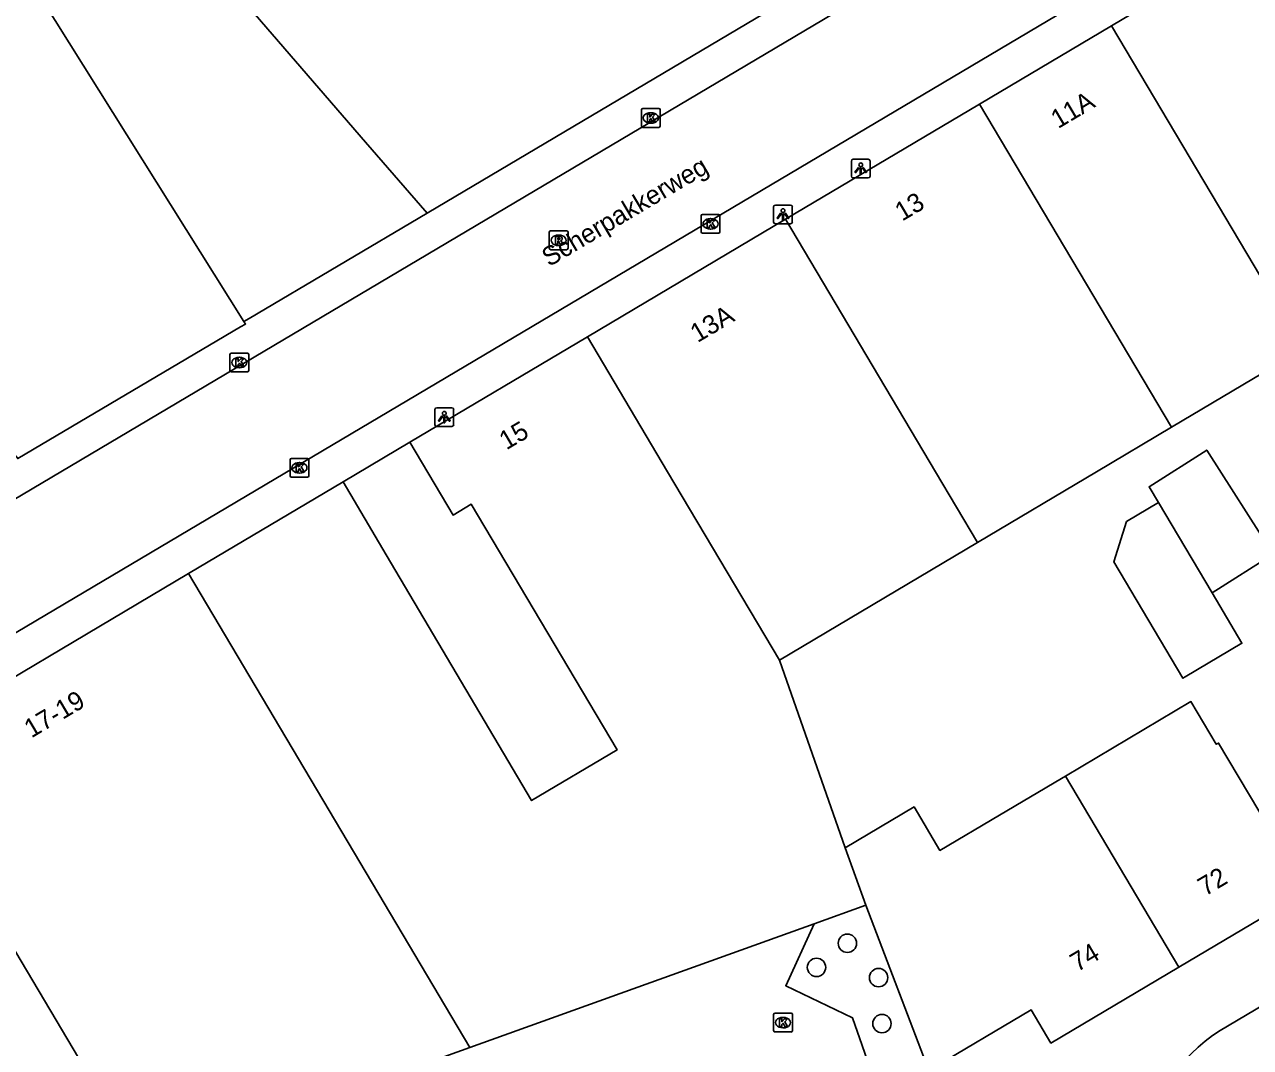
# Model space of a CAD drawing. Extents: x 159503 to 160347, y 382525 to 383272.
# Drawn here: x 159623.7 to 159688.9, y 382969.4 to 383023.8 of the extents above; entities that cross this region are included whole.
import ezdxf

# ---------------------------------------------------------------- set-up
doc = ezdxf.new("R2010")
doc.units = 0
for name, color, linetype in [('IMGEO_Boom', 7, 'Continuous'), ('IMGEO_Kolk', 7, 'Continuous'), ('IMGEO_Lichtpunt', 7, 'Continuous'), ('IMGEO_Openbare_ruimte_label', 7, 'Continuous'), ('IMGEO_Pand', 7, 'Continuous'), ('IMGEO_Pand_nummerreeks', 7, 'Continuous'), ('IMGEO_Parkeervlak_open', 7, 'Continuous'), ('IMGEO_Rijbaan_lokaal_open', 7, 'Continuous'), ('IMGEO_Rioolput', 7, 'Continuous'), ('IMGEO_Voetpad_open', 7, 'Continuous')]:
    doc.layers.add(name, color=color, linetype=linetype)

msp = doc.modelspace()

# ---------------------------------------------------------------- linework, layer by layer
at = {"layer": 'IMGEO_Boom'}
for centre in [(159667.462, 382974.908), (159665.819, 382973.625), (159669.12, 382973.079), (159669.302, 382970.634)]:
    msp.add_circle(centre, 0.489, dxfattribs=at)
at = {"layer": 'IMGEO_Kolk'}
for p, q in [((159656.504, 383018.408), (159656.504, 383019.26)), ((159656.579, 383019.334), (159657.431, 383019.334)), ((159657.505, 383019.26), (159657.505, 383018.408)), ((159657.015, 383018.554), (159656.99, 383018.554)), ((159656.992, 383019.114), (159657.017, 383019.114)), ((159657.431, 383018.334), (159656.579, 383018.334)), ((159659.68, 383012.776), (159659.68, 383013.628)), ((159659.755, 383013.702), (159660.607, 383013.702)), ((159660.168, 383013.482), (159660.193, 383013.482)), ((159660.681, 383013.628), (159660.681, 383012.776)), ((159660.607, 383012.702), (159659.755, 383012.702)), ((159660.191, 383012.922), (159660.166, 383012.922)), ((159634.611, 383005.389), (159634.611, 383006.241)), ((159634.686, 383006.315), (159635.538, 383006.315)), ((159635.612, 383006.241), (159635.612, 383005.389)), ((159635.122, 383005.535), (159635.097, 383005.535)), ((159635.099, 383006.095), (159635.124, 383006.095)), ((159635.538, 383005.315), (159634.686, 383005.315)), ((159637.809, 382999.786), (159637.809, 383000.638)), ((159637.884, 383000.712), (159638.736, 383000.712)), ((159638.297, 383000.492), (159638.322, 383000.492)), ((159638.81, 383000.638), (159638.81, 382999.786)), ((159638.736, 382999.712), (159637.884, 382999.712)), ((159638.32, 382999.932), (159638.295, 382999.932)), ((159663.536, 382970.26), (159663.536, 382971.112)), ((159663.611, 382971.186), (159664.463, 382971.186)), ((159664.024, 382970.966), (159664.049, 382970.966)), ((159664.537, 382971.112), (159664.537, 382970.26)), ((159664.047, 382970.406), (159664.022, 382970.406)), ((159664.463, 382970.186), (159663.611, 382970.186))]:
    msp.add_line(p, q, dxfattribs=at)
for points in [[(159656.504, 383018.408), (159656.504, 383019.26)], [(159656.579, 383019.334), (159657.431, 383019.334)], [(159657.505, 383019.26), (159657.505, 383018.408)], [(159656.825, 383019.034), (159656.948, 383019.034), (159656.948, 383018.883), (159657.078, 383019.034), (159657.242, 383019.034), (159657.096, 383018.883), (159657.249, 383018.634), (159657.097, 383018.634), (159657.012, 383018.798), (159656.948, 383018.731), (159656.948, 383018.634), (159656.825, 383018.634), (159656.825, 383019.034)], [(159657.431, 383018.334), (159656.579, 383018.334)], [(159659.68, 383012.776), (159659.68, 383013.628)], [(159659.755, 383013.702), (159660.607, 383013.702)], [(159660.001, 383013.402), (159660.124, 383013.402), (159660.124, 383013.251), (159660.254, 383013.402), (159660.418, 383013.402), (159660.272, 383013.251), (159660.425, 383013.002), (159660.273, 383013.002), (159660.188, 383013.166), (159660.124, 383013.099), (159660.124, 383013.002), (159660.001, 383013.002), (159660.001, 383013.402)], [(159660.681, 383013.628), (159660.681, 383012.776)], [(159660.607, 383012.702), (159659.755, 383012.702)], [(159634.611, 383005.389), (159634.611, 383006.241)], [(159634.686, 383006.315), (159635.538, 383006.315)], [(159635.612, 383006.241), (159635.612, 383005.389)], [(159634.932, 383006.015), (159635.055, 383006.015), (159635.055, 383005.864), (159635.185, 383006.015), (159635.349, 383006.015), (159635.203, 383005.864), (159635.356, 383005.615), (159635.204, 383005.615), (159635.119, 383005.779), (159635.055, 383005.712), (159635.055, 383005.615), (159634.932, 383005.615), (159634.932, 383006.015)], [(159635.538, 383005.315), (159634.686, 383005.315)], [(159637.809, 382999.786), (159637.809, 383000.638)], [(159637.884, 383000.712), (159638.736, 383000.712)], [(159638.13, 383000.412), (159638.253, 383000.412), (159638.253, 383000.261), (159638.383, 383000.412), (159638.547, 383000.412), (159638.401, 383000.261), (159638.554, 383000.012), (159638.402, 383000.012), (159638.317, 383000.176), (159638.253, 383000.109), (159638.253, 383000.012), (159638.13, 383000.012), (159638.13, 383000.412)], [(159638.81, 383000.638), (159638.81, 382999.786)], [(159638.736, 382999.712), (159637.884, 382999.712)], [(159663.536, 382970.26), (159663.536, 382971.112)], [(159663.611, 382971.186), (159664.463, 382971.186)], [(159664.537, 382971.112), (159664.537, 382970.26)], [(159663.857, 382970.886), (159663.98, 382970.886), (159663.98, 382970.735), (159664.11, 382970.886), (159664.274, 382970.886), (159664.128, 382970.735), (159664.281, 382970.486), (159664.129, 382970.486), (159664.044, 382970.65), (159663.98, 382970.583), (159663.98, 382970.486), (159663.857, 382970.486), (159663.857, 382970.886)], [(159664.463, 382970.186), (159663.611, 382970.186)]]:
    msp.add_lwpolyline(points, dxfattribs=at)
for centre, start, end in [((159656.581, 383019.258), 91.55205, 178.44795), ((159656.581, 383019.258), 91.55205, 178.44795), ((159657.429, 383019.258), 1.55205, 88.44795), ((159657.429, 383019.258), 1.55205, 88.44795), ((159656.581, 383018.41), 181.55205, 268.44795), ((159656.581, 383018.41), 181.55205, 268.44795), ((159657.429, 383018.41), 271.55205, 358.44795), ((159657.429, 383018.41), 271.55205, 358.44795), ((159659.757, 383013.626), 91.55205, 178.44795), ((159659.757, 383013.626), 91.55205, 178.44795), ((159660.605, 383013.626), 1.55205, 88.44795), ((159660.605, 383013.626), 1.55205, 88.44795), ((159659.757, 383012.778), 181.55205, 268.44795), ((159659.757, 383012.778), 181.55205, 268.44795), ((159660.605, 383012.778), 271.55205, 358.44795), ((159660.605, 383012.778), 271.55205, 358.44795), ((159634.688, 383006.239), 91.55205, 178.44795), ((159634.688, 383006.239), 91.55205, 178.44795), ((159635.536, 383006.239), 1.55205, 88.44795), ((159635.536, 383006.239), 1.55205, 88.44795), ((159634.688, 383005.391), 181.55205, 268.44795), ((159634.688, 383005.391), 181.55205, 268.44795), ((159635.536, 383005.391), 271.55205, 358.44795), ((159635.536, 383005.391), 271.55205, 358.44795), ((159637.886, 383000.636), 91.55205, 178.44795), ((159637.886, 383000.636), 91.55205, 178.44795), ((159638.734, 383000.636), 1.55205, 88.44795), ((159638.734, 383000.636), 1.55205, 88.44795), ((159637.886, 382999.788), 181.55205, 268.44795), ((159637.886, 382999.788), 181.55205, 268.44795), ((159638.734, 382999.788), 271.55205, 358.44795), ((159638.734, 382999.788), 271.55205, 358.44795), ((159663.613, 382971.11), 91.55205, 178.44795), ((159663.613, 382971.11), 91.55205, 178.44795), ((159664.461, 382971.11), 1.55205, 88.44795), ((159664.461, 382971.11), 1.55205, 88.44795), ((159663.613, 382970.262), 181.55205, 268.44795), ((159663.613, 382970.262), 181.55205, 268.44795), ((159664.461, 382970.262), 271.55205, 358.44795), ((159664.461, 382970.262), 271.55205, 358.44795)]:
    msp.add_arc(centre, 0.0765, start, end, dxfattribs=at)
for centre, major_axis, ratio, start_param, end_param in [((159656.991, 383018.834), (-0.387, 0.002), 0.722429, 4.712389, 7.853982), ((159657.016, 383018.834), (-0.39, 0.002), 0.717154, 1.570796, 4.712389), ((159660.167, 383013.202), (-0.387, 0.002), 0.722429, 4.712389, 7.853982), ((159660.192, 383013.202), (-0.39, 0.002), 0.717154, 1.570796, 4.712389), ((159635.098, 383005.815), (-0.387, 0.002), 0.722429, 4.712389, 7.853982), ((159635.123, 383005.815), (-0.39, 0.002), 0.717154, 1.570796, 4.712389), ((159638.296, 383000.212), (-0.387, 0.002), 0.722429, 4.712389, 7.853982), ((159638.321, 383000.212), (-0.39, 0.002), 0.717154, 1.570796, 4.712389), ((159664.023, 382970.686), (-0.387, 0.002), 0.722429, 4.712389, 7.853982), ((159664.048, 382970.686), (-0.39, 0.002), 0.717154, 1.570796, 4.712389)]:
    msp.add_ellipse(centre, major_axis=major_axis, ratio=ratio, start_param=start_param, end_param=end_param, dxfattribs=at)
at = {"layer": 'IMGEO_Lichtpunt'}
for p, q in [((159668.575, 383016.636), (159667.767, 383016.636)), ((159668.575, 383016.636), (159667.767, 383016.636)), ((159667.673, 383016.541), (159667.673, 383015.734)), ((159667.673, 383016.541), (159667.673, 383015.734)), ((159668.669, 383015.734), (159668.669, 383016.541)), ((159668.669, 383015.734), (159668.669, 383016.541)), ((159667.767, 383015.64), (159668.575, 383015.64)), ((159667.767, 383015.64), (159668.575, 383015.64)), ((159663.536, 383014.103), (159663.536, 383013.296)), ((159663.536, 383014.103), (159663.536, 383013.296)), ((159664.438, 383014.198), (159663.63, 383014.198)), ((159664.438, 383014.198), (159663.63, 383014.198)), ((159664.532, 383013.296), (159664.532, 383014.103)), ((159664.532, 383013.296), (159664.532, 383014.103)), ((159663.63, 383013.202), (159664.438, 383013.202)), ((159663.63, 383013.202), (159664.438, 383013.202)), ((159645.518, 383003.315), (159645.518, 383002.508)), ((159645.518, 383003.315), (159645.518, 383002.508)), ((159646.42, 383003.41), (159645.612, 383003.41)), ((159646.42, 383003.41), (159645.612, 383003.41)), ((159646.514, 383002.508), (159646.514, 383003.315)), ((159646.514, 383002.508), (159646.514, 383003.315)), ((159645.612, 383002.414), (159646.42, 383002.414)), ((159645.612, 383002.414), (159646.42, 383002.414))]:
    msp.add_line(p, q, dxfattribs=at)
for points in [[(159668.047, 383016.205), (159668.086, 383016.177), (159667.898, 383015.915), (159667.86, 383015.942), (159668.047, 383016.205)], [(159668.149, 383016.157), (159668.196, 383016.157), (159668.196, 383015.835), (159668.149, 383015.835), (159668.149, 383016.157)], [(159668.259, 383016.177), (159668.297, 383016.204), (159668.484, 383015.942), (159668.445, 383015.914), (159668.259, 383016.177)], [(159663.91, 383013.767), (159663.949, 383013.739), (159663.761, 383013.477), (159663.723, 383013.504), (159663.91, 383013.767)], [(159664.012, 383013.719), (159664.059, 383013.719), (159664.059, 383013.397), (159664.012, 383013.397), (159664.012, 383013.719)], [(159664.122, 383013.739), (159664.16, 383013.766), (159664.347, 383013.504), (159664.308, 383013.476), (159664.122, 383013.739)], [(159645.892, 383002.979), (159645.931, 383002.951), (159645.743, 383002.689), (159645.705, 383002.716), (159645.892, 383002.979)], [(159645.994, 383002.931), (159646.041, 383002.931), (159646.041, 383002.609), (159645.994, 383002.609), (159645.994, 383002.931)], [(159646.104, 383002.951), (159646.142, 383002.978), (159646.329, 383002.716), (159646.29, 383002.688), (159646.104, 383002.951)]]:
    msp.add_lwpolyline(points, dxfattribs=at)
for centre in [(159668.172, 383016.339), (159664.035, 383013.901), (159646.017, 383003.113)]:
    msp.add_circle(centre, 0.0994, dxfattribs=at)
for centre, start, end in [((159667.767, 383016.541), 90, 180), ((159667.767, 383016.541), 90, 180), ((159668.575, 383016.541), 0, 90), ((159668.575, 383016.541), 0, 90), ((159667.767, 383015.734), 180, 270), ((159667.767, 383015.734), 180, 270), ((159668.575, 383015.734), 270, 0), ((159668.575, 383015.734), 270, 360), ((159663.63, 383014.103), 90, 180), ((159663.63, 383014.103), 90, 180), ((159664.438, 383014.103), 0, 90), ((159664.438, 383014.103), 0, 90), ((159663.63, 383013.296), 180, 270), ((159663.63, 383013.296), 180, 270), ((159664.438, 383013.296), 270, 0), ((159664.438, 383013.296), 270, 360), ((159645.612, 383003.315), 90, 180), ((159645.612, 383003.315), 90, 180), ((159646.42, 383003.315), 0, 90), ((159646.42, 383003.315), 0, 90), ((159645.612, 383002.508), 180, 270), ((159645.612, 383002.508), 180, 270), ((159646.42, 383002.508), 270, 0), ((159646.42, 383002.508), 270, 360)]:
    msp.add_arc(centre, 0.0946, start, end, dxfattribs=at)
at = {"layer": 'IMGEO_Pand'}
for points in [[(159681.512, 383023.741), (159707.235, 383039.014)], [(159630.675, 383036.596), (159629.723, 383035.994), (159627.256, 383034.416), (159641.831, 383017.554), (159645.1, 383013.771)], [(159635.355, 383008.004), (159621.4, 383030.261), (159609.307, 383022.512)], [(159645.1, 383013.771), (159672.277, 383029.896)], [(159674.495, 383019.575), (159681.512, 383023.741)], [(159691.726, 383006.538), (159681.512, 383023.741)], [(159664.169, 383013.444), (159674.495, 383019.575)], [(159674.495, 383019.575), (159684.709, 383002.371)], [(159653.631, 383007.187), (159664.169, 383013.444)], [(159664.169, 383013.444), (159672.152, 383000), (159674.384, 382996.239)], [(159623.224, 383000.858), (159623.323, 383000.702), (159635.177, 383007.713), (159635.443, 383007.863), (159635.355, 383008.004)], [(159644.178, 383001.574), (159653.631, 383007.187)], [(159663.847, 382989.981), (159657.898, 383000), (159653.631, 383007.187)], [(159691.726, 383006.538), (159684.709, 383002.371)], [(159684.709, 383002.371), (159680.717, 383000), (159674.384, 382996.239)], [(159640.635, 382999.47), (159642.929, 382995.586), (159650.661, 382982.501), (159655.211, 382985.203), (159647.452, 382998.271), (159646.481, 382997.695), (159644.178, 383001.574)], [(159684.01, 382998.362), (159683.51, 382999.204), (159686.583, 383001.161), (159690.111, 382995.622), (159686.864, 382993.555)], [(159632.4, 382994.581), (159640.635, 382999.47)], [(159686.864, 382993.555), (159688.454, 382990.878), (159685.435, 382989.085), (159685.312, 382989.012), (159681.628, 382995.217), (159682.313, 382997.354), (159684.01, 382998.362)], [(159684.01, 382998.362), (159686.864, 382993.555)], [(159674.384, 382996.239), (159663.847, 382989.981)], [(159616.76, 382985.295), (159632.4, 382994.581)], [(159647.373, 382969.363), (159632.4, 382994.581)], [(159663.847, 382989.981), (159667.344, 382979.99)], [(159679.058, 382983.809), (159685.737, 382987.769), (159687.083, 382985.498), (159687.206, 382985.567), (159689.342, 382981.964), (159691.891, 382977.662), (159685.088, 382973.63)], [(159616.76, 382985.295), (159629.938, 382963.1)], [(159667.344, 382979.99), (159671.009, 382982.163), (159672.381, 382979.849), (159675.547, 382981.727), (159678.85, 382983.686), (159679.058, 382983.809)], [(159685.088, 382973.63), (159679.058, 382983.809)], [(159667.344, 382979.99), (159668.441, 382976.932)], [(159665.691, 382975.944), (159668.441, 382976.932)], [(159668.441, 382976.932), (159671.788, 382968.131)], [(159647.373, 382969.363), (159665.691, 382975.944)], [(159685.088, 382973.63), (159678.287, 382969.599), (159677.242, 382971.363), (159671.788, 382968.131)], [(159629.938, 382963.1), (159647.373, 382969.363)]]:
    msp.add_lwpolyline(points, dxfattribs=at)
at = {"layer": 'IMGEO_Parkeervlak_open'}
msp.add_lwpolyline([(159672.61, 382965.844), (159669.28, 382966.514), (159667.737, 382970.948), (159664.183, 382972.651), (159665.691, 382975.944)], dxfattribs=at)
at = {"layer": 'IMGEO_Rijbaan_lokaal_open'}
for points in [[(159724.205, 383058.665), (159687.242, 383036.582), (159585.591, 382976.257)], [(159719.236, 383048.422), (159586.71, 382969.778)]]:
    msp.add_lwpolyline(points, dxfattribs=at)
at = {"layer": 'IMGEO_Rioolput'}
for p, q in [((159651.599, 383011.896), (159651.599, 383012.748)), ((159651.674, 383012.822), (159652.526, 383012.822)), ((159652.6, 383012.748), (159652.6, 383011.896)), ((159652.11, 383012.042), (159652.085, 383012.042)), ((159652.087, 383012.602), (159652.112, 383012.602)), ((159652.526, 383011.822), (159651.674, 383011.822))]:
    msp.add_line(p, q, dxfattribs=at)
for points in [[(159651.599, 383011.896), (159651.599, 383012.748)], [(159651.674, 383012.822), (159652.526, 383012.822)], [(159652.6, 383012.748), (159652.6, 383011.896)], [(159652.188, 383012.52), (159651.936, 383012.522), (159651.936, 383012.122)], [(159651.936, 383012.122), (159652.06, 383012.122), (159652.06, 383012.284), (159652.071, 383012.284)], [(159652.114, 383012.441), (159652.06, 383012.441), (159652.06, 383012.36)], [(159652.06, 383012.36), (159652.112, 383012.36)], [(159652.118, 383012.255), (159652.189, 383012.122), (159652.329, 383012.122), (159652.264, 383012.248)], [(159652.526, 383011.822), (159651.674, 383011.822)]]:
    msp.add_lwpolyline(points, dxfattribs=at)
for centre, radius, start, end in [((159651.676, 383012.746), 0.0765, 91.55205, 178.44795), ((159651.676, 383012.746), 0.0765, 91.55205, 178.44795), ((159652.524, 383012.746), 0.0765, 1.55205, 88.44795), ((159652.524, 383012.746), 0.0765, 1.55205, 88.44795), ((159652.07, 383012.231), 0.0533, 26.02933, 88.69889), ((159652.096, 383012.549), 0.19, 274.7715, 282.96867), ((159652.12, 383012.345), 0.0964, 77.00612, 93.18647), ((159652.134, 383012.402), 0.0378, 276.66336, 79.67722), ((159652.187, 383012.41), 0.109, 350.36119, 89.41601), ((159652.185, 383012.41), 0.112, 277.58423, 350.98172), ((159652.169, 383012.195), 0.108, 29.51342, 73.79051), ((159651.676, 383011.898), 0.0765, 181.55205, 268.44795), ((159651.676, 383011.898), 0.0765, 181.55205, 268.44795), ((159652.524, 383011.898), 0.0765, 271.55205, 358.44795), ((159652.524, 383011.898), 0.0765, 271.55205, 358.44795)]:
    msp.add_arc(centre, radius, start, end, dxfattribs=at)
for centre, major_axis, ratio, start_param, end_param in [((159652.086, 383012.322), (-0.387, 0.002), 0.722429, 4.712389, 7.853982), ((159652.111, 383012.322), (-0.39, 0.002), 0.717154, 1.570796, 4.712389)]:
    msp.add_ellipse(centre, major_axis=major_axis, ratio=ratio, start_param=start_param, end_param=end_param, dxfattribs=at)
at = {"layer": 'IMGEO_Voetpad_open'}
for points in [[(159635.355, 383008.004), (159635.632, 383008.168), (159645.1, 383013.771)], [(159640.635, 382999.47), (159644.178, 383001.574)], [(159687.291, 382970.274), (159725.98, 382993.204)]]:
    msp.add_lwpolyline(points, dxfattribs=at)
msp.add_arc((159693.347, 382961.21), 10.901, 123.74738, 164.84303, dxfattribs=at)

# ---------------------------------------------------------------- texts
at = {"layer": 'IMGEO_Openbare_ruimte_label'}
msp.add_text('Scherpakkerweg', height=1, rotation=30.66893, dxfattribs=at).set_placement((159651.588, 383010.891))
at = {"layer": 'IMGEO_Pand_nummerreeks'}
for s, rotation, p in [('11A', 30.69765, (159678.669, 383018.239)), ('13', 30.69947, (159670.374, 383013.314)), ('13A', 30.69998, (159659.487, 383006.85)), ('15', 30.69908, (159649.319, 383001.138)), ('17-19', 30.69905, (159624.048, 382985.807)), ('72', 30.65494, (159686.491, 382977.391)), ('74', 30.65494, (159679.692, 382973.36))]:
    msp.add_text(s, height=1, rotation=rotation, dxfattribs=at).set_placement(p)

doc.saveas('drawing.dxf')
